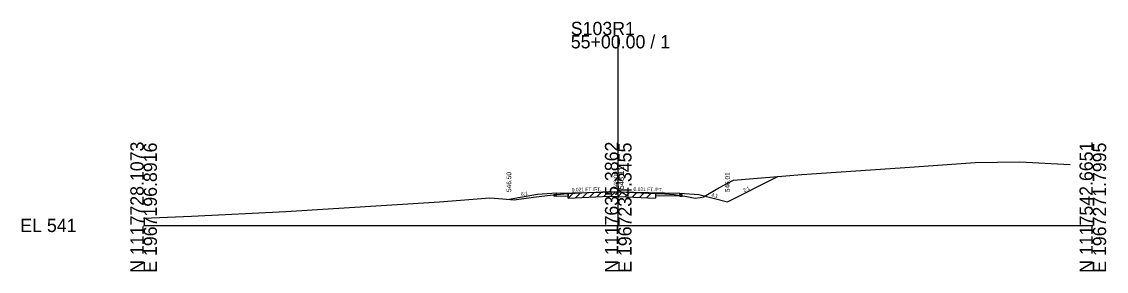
# Model space of a CAD drawing. Extents: x -26 to 203, y -10 to 12018.
# Drawn here: x -25.7 to 202.8, y 1990.3 to 2043 of the extents above; entities that cross this region are included whole.
import ezdxf

# ---------------------------------------------------------------- set-up
doc = ezdxf.new("R2010")
doc.units = 0
for name, color, linetype in [('Level 10', 7, 'Continuous'), ('Level 11', 7, 'Continuous'), ('Level 12', 7, 'Continuous'), ('Level 32', 7, 'Continuous'), ('Level 33', 7, 'Continuous'), ('Level 59', 7, 'Continuous'), ('Level 6', 7, 'Continuous'), ('Level 60', 7, 'Continuous'), ('Level 61', 7, 'Continuous'), ('Level 63', 7, 'Continuous'), ('Level 7', 7, 'Continuous')]:
    doc.layers.add(name, color=color, linetype=linetype)

msp = doc.modelspace()

# ---------------------------------------------------------------- linework, layer by layer
at = {"layer": 'Level 11'}
for p, q in [((86.5, 2006.52), (87, 2006.53)), ((87, 2006.53), (87, 2006.84)), ((113, 2006.53), (113, 2006.84)), ((113.5, 2006.52), (113, 2006.53)), ((86.5, 2006.16), (86.5, 2006.52)), ((87, 2006.17), (86.5, 2006.16)), ((113, 2006.17), (113.5, 2006.16)), ((113.5, 2006.16), (113.5, 2006.52))]:
    msp.add_line(p, q, dxfattribs=at)
at = {"layer": 'Level 12'}
for p, q in [((89.47, 2006.76), (89.47, 2006.22)), ((107.83, 2006.77), (107.83, 2006.27)), ((87, 2006.17), (89.47, 2006.22)), ((113, 2006.17), (107.83, 2006.27))]:
    msp.add_line(p, q, dxfattribs=at)
at = {"layer": 'Level 59'}
for p, q in [((87, 2006.84), (100, 2007.11)), ((100, 2007.11), (113, 2006.84))]:
    msp.add_line(p, q, dxfattribs=at)
at = {"layer": 'Level 6'}
for p, q in [((87, 2006.84), (83, 2006.51)), ((113, 2006.84), (117, 2006.51))]:
    msp.add_line(p, q, dxfattribs=at)
at = {"layer": 'Level 60'}
for p, q in [((175.24, 2013.31), (184.59, 2013.39)), ((184.59, 2013.39), (195.21, 2012.86)), ((138.66, 2010.75), (161.43, 2012.33)), ((161.43, 2012.33), (175.24, 2013.31)), ((121.23, 2007.94), (124.29, 2009.55)), ((124.29, 2009.55), (138.66, 2010.75)), ((86.31, 2006.46), (87.84, 2006.61)), ((87.84, 2006.61), (89.47, 2006.76)), ((89.47, 2006.76), (93.8, 2006.96)), ((93.8, 2006.96), (98.18, 2007.17)), ((98.18, 2007.17), (100, 2007.09)), ((100, 2007.09), (103.27, 2006.96)), ((103.27, 2006.96), (107.83, 2006.77)), ((107.83, 2006.77), (109.84, 2006.65)), ((109.84, 2006.65), (111.8, 2006.5)), ((117.94, 2006.03), (121.23, 2007.94)), ((29.98, 2002.94), (62.33, 2004.98)), ((62.33, 2004.98), (72.93, 2005.81)), ((72.93, 2005.81), (75.66, 2005.6)), ((75.66, 2005.6), (78.05, 2005.42)), ((78.05, 2005.42), (82.15, 2005.96)), ((82.15, 2005.96), (86.31, 2006.46)), ((111.8, 2006.5), (114.47, 2006.11)), ((114.47, 2006.11), (116.19, 2005.78)), ((116.19, 2005.78), (117.24, 2005.93)), ((117.24, 2005.93), (117.94, 2006.03)), ((10.07, 2001.92), (29.98, 2002.94)), ((0, 2001.5), (10.07, 2001.92))]:
    msp.add_line(p, q, dxfattribs=at)
at = {"layer": 'Level 61'}
for p, q in [((89.47, 2005.76), (90.52, 2006.81)), ((89.47, 2005.76), (89.47, 2006.76)), ((90.97, 2005.83), (92.02, 2006.88)), ((92.47, 2005.9), (93.52, 2006.95)), ((93.97, 2005.97), (95.02, 2007.02)), ((95.47, 2006.04), (96.52, 2007.09)), ((96.97, 2006.11), (98.02, 2007.16)), ((98.47, 2006.16), (99.43, 2007.12)), ((99.97, 2006.09), (100.93, 2007.06)), ((101.47, 2006.03), (102.43, 2006.99)), ((102.97, 2005.97), (103.93, 2006.93)), ((104.47, 2005.91), (105.43, 2006.87)), ((105.97, 2005.85), (106.93, 2006.81)), ((107.83, 2006.77), (107.83, 2005.77)), ((89.47, 2005.76), (93.8, 2005.96)), ((93.8, 2005.96), (98.18, 2006.17)), ((98.18, 2006.17), (100, 2006.09)), ((100, 2006.09), (103.27, 2005.96)), ((103.27, 2005.96), (107.83, 2005.77))]:
    msp.add_line(p, q, dxfattribs=at)
at = {"layer": 'Level 63'}
for p, q in [((100, 2000), (100, 2040.17)), ((0, 2000), (100, 2000)), ((100, 2000), (200, 2000))]:
    msp.add_line(p, q, dxfattribs=at)
at = {"layer": 'Level 7'}
for p, q in [((123, 2005.01), (133.65, 2010.33)), ((83, 2006.51), (76.99, 2005.5)), ((117, 2006.51), (123, 2005.01))]:
    msp.add_line(p, q, dxfattribs=at)

# ---------------------------------------------------------------- texts
at = {"layer": 'Level 10'}
msp.add_text(' 548.09', height=0.9, rotation=90, dxfattribs=at).set_placement((99.95, 2007.25))
at = {"layer": 'Level 32'}
for s, rotation, p in [('6:1', 9.4623, (79.59, 2006.19)), ('0.021 FT./FT.', 1.1916, (90.21, 2007.16)), ('0.021 FT./FT.', 358.8084, (103.22, 2007.29)), ('4:1', 345.9638, (119.55, 2006.13)), ('2:1', 26.5651, (126.53, 2006.98))]:
    msp.add_text(s, height=0.75, rotation=rotation, dxfattribs=at).set_placement(p)
at = {"layer": 'Level 33'}
for s, p in [('546.50', (77.46, 2007.05)), ('546.01', (123.5, 2007.01))]:
    msp.add_text(s, height=1, rotation=90, dxfattribs=at).set_placement(p)
at = {"layer": 'Level 59'}
msp.add_text(' 548.11', height=1.2, rotation=90, dxfattribs=at).set_placement((101.2, 2007.11))
at = {"layer": 'Level 63'}
for s, p in [('S103R1', (90, 2040.17)), ('55+00.00 / 1', (90, 2037.37)), ('EL 541', (-26, 1998.6))]:
    msp.add_text(s, height=2.8, dxfattribs=at).set_placement(p)
for s, p in [('N 1117728.1073', (0, 1990)), ('E 1967196.8916', (2.8, 1990)), ('N 1117635.3862', (100, 1990)), ('E 1967234.3455', (102.8, 1990)), ('N 1117542.6651', (200, 1990)), ('E 1967271.7995', (202.8, 1990))]:
    msp.add_text(s, height=2.8, rotation=90, dxfattribs=at).set_placement(p)

doc.saveas('drawing.dxf')
